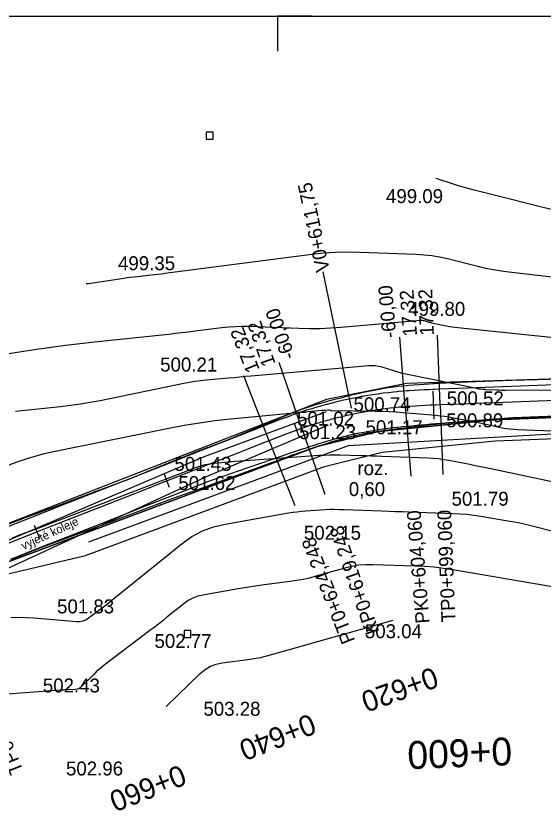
# Model space of a CAD drawing. Extents: x -636600 to -628587, y -1090963 to -1085869.
# Drawn here: x -629674.7 to -629599.1, y -1089305.8 to -1089190 of the extents above; entities that cross this region are included whole.
import ezdxf

# ---------------------------------------------------------------- set-up
doc = ezdxf.new("R2010")
doc.units = 0
for name, color, linetype in [('01_PARCELY_NÁVRH_PC', 7, 'Continuous'), ('06_ÚSES_IP_NAVRH', 7, 'Continuous'), ('08_LEGENDA_HV', 7, 'Continuous'), ('15', 7, 'Continuous'), ('40', 7, 'Continuous'), ('52', 7, 'Continuous'), ('Ex_Major Contours', 7, 'Continuous'), ('Ex_Minor Contours', 7, 'Continuous'), ('HEKTOMETRY100', 7, 'Continuous'), ('HEKTOMETRY20', 7, 'Continuous'), ('HL_BODY', 7, 'Continuous'), ('koty_vše', 7, 'Continuous'), ('POLOMERY', 7, 'Continuous'), ('popis', 7, 'Continuous'), ('situace_osa', 7, 'Continuous'), ('situace_těleso', 7, 'Continuous'), ('situace_vozovka', 7, 'Continuous'), ('VRCHOLY', 7, 'Continuous')]:
    doc.layers.add(name, color=color, linetype=linetype)

msp = doc.modelspace()

# ---------------------------------------------------------------- linework, layer by layer
at = {"layer": '01_PARCELY_NÁVRH_PC'}
for points in [[(-629219.96, -1089257.88), (-629393.2, -1089239.09), (-629404.84, -1089238.49), (-629532.17, -1089240), (-629618.76, -1089242.62), (-629630.23, -1089244.94), (-629692.43, -1089269.15), (-629702.88, -1089275.33), (-629709.57, -1089280.47), (-629719.03, -1089292.94), (-629735.64, -1089330.23), (-629741.78, -1089338.98), (-629748.13, -1089344.96), (-629754.15, -1089347.42), (-629771.79, -1089346.48), (-629796.88, -1089348.54), (-629815.64, -1089354.58), (-629845.21, -1089367.17), (-629847.27, -1089367.82)], [(-629847.27, -1089372.98), (-629830.39, -1089366.4), (-629824.12, -1089366.02), (-629805.68, -1089358.95), (-629799.19, -1089354.87), (-629780.4, -1089352.5), (-629755.55, -1089353.84), (-629747.35, -1089351.41), (-629741.75, -1089348.16), (-629736.53, -1089343.03), (-629730.9, -1089333.83), (-629715.8, -1089299.08), (-629708.65, -1089288.23), (-629702.22, -1089281.94), (-629693.51, -1089276), (-629681.41, -1089270.27), (-629631.42, -1089251.64), (-629622.77, -1089249.5), (-629606.23, -1089247.86), (-629544.07, -1089245.47), (-629416.57, -1089243.64)]]:
    msp.add_lwpolyline(points, dxfattribs=at)
msp.add_lwpolyline([(-629391.26, -1089246.28), (-629410.87, -1089245.47), (-629416.57, -1089243.64), (-629544.07, -1089245.47), (-629606.23, -1089247.86), (-629622.77, -1089249.5), (-629631.42, -1089251.64), (-629681.41, -1089270.27), (-629685.4, -1089272.16), (-629664.77, -1089267.27), (-629630.53, -1089254.51), (-629622.26, -1089252.46), (-629606.02, -1089250.85), (-629543.99, -1089248.47), (-629417.02, -1089246.65)], close=True, dxfattribs=at)
at = {"layer": '06_ÚSES_IP_NAVRH'}
msp.add_lwpolyline([(-629416.96, -1089245.08), (-629541.78, -1089246.72), (-629627.12, -1089251.56), (-629664.34, -1089265.4)], dxfattribs=at)
at = {"layer": '08_LEGENDA_HV'}
msp.add_line((-629847.27, -1089189.97), (-629007.27, -1089189.97), dxfattribs=at)
msp.add_lwpolyline([(-629632.27, -1089189.97), (-629637.27, -1089189.97), (-629637.27, -1089194.97)], dxfattribs=at)
at = {"layer": '40'}
for p, q in [((-629647.87, -1089253.16), (-629630.2, -1089246.66)), ((-629630, -1089248.61), (-629647.24, -1089255.9)), ((-629680.71, -1089267.18), (-629647.87, -1089253.16)), ((-629647.24, -1089255.9), (-629679.33, -1089270.72))]:
    msp.add_line(p, q, dxfattribs=at)
at = {"layer": '52'}
for points in [[(-629647.47, -1089207.61), (-629646.47, -1089207.61), (-629646.47, -1089206.61), (-629647.47, -1089206.61)], [(-629650.65, -1089279.05), (-629649.65, -1089279.05), (-629649.65, -1089278.05), (-629650.65, -1089278.05)]]:
    msp.add_lwpolyline(points, close=True, dxfattribs=at)
at = {"layer": 'Ex_Major Contours'}
for points in [[(-629689.6, -1089240.47), (-629671.78, -1089237.73), (-629669.71, -1089237.43), (-629667.63, -1089237.15), (-629665.55, -1089236.89), (-629663.47, -1089236.66), (-629652.86, -1089235.55), (-629651.91, -1089235.44), (-629650.95, -1089235.34), (-629650, -1089235.22), (-629649.05, -1089235.1), (-629645.24, -1089234.61), (-629644.29, -1089234.5), (-629643.34, -1089234.44), (-629642.38, -1089234.42), (-629641.42, -1089234.43), (-629634.2, -1089234.71), (-629632.68, -1089234.74), (-629631.15, -1089234.73), (-629629.63, -1089234.67), (-629628.11, -1089234.56), (-629616.75, -1089233.56), (-629616.61, -1089233.55), (-629616.48, -1089233.56), (-629616.35, -1089233.58), (-629616.21, -1089233.62), (-629615.69, -1089233.78), (-629615.56, -1089233.82), (-629615.43, -1089233.86), (-629615.29, -1089233.89), (-629615.16, -1089233.92), (-629613.01, -1089234.36), (-629612.6, -1089234.44), (-629612.19, -1089234.5), (-629611.79, -1089234.56), (-629611.38, -1089234.61), (-629598.07, -1089235.97)], [(-629588.58, -1089273.37), (-629612.11, -1089269.36), (-629613.45, -1089269.15), (-629614.8, -1089268.99), (-629616.15, -1089268.88), (-629617.5, -1089268.81), (-629623.57, -1089268.61), (-629624.59, -1089268.61), (-629625.61, -1089268.7), (-629626.62, -1089268.86), (-629627.61, -1089269.1), (-629631.74, -1089270.28), (-629632.65, -1089270.52), (-629633.57, -1089270.73), (-629634.5, -1089270.9), (-629635.43, -1089271.04), (-629639.17, -1089271.52), (-629640.1, -1089271.65), (-629641.03, -1089271.79), (-629641.96, -1089271.93), (-629642.89, -1089272.09), (-629647.93, -1089272.96), (-629648.68, -1089273.14), (-629649.38, -1089273.41), (-629650.05, -1089273.76), (-629650.67, -1089274.2), (-629653.1, -1089276.15), (-629653.7, -1089276.64), (-629654.32, -1089277.12), (-629654.93, -1089277.6), (-629655.55, -1089278.07), (-629662.09, -1089283.02), (-629662.49, -1089283.33), (-629662.87, -1089283.66), (-629663.24, -1089283.99), (-629663.6, -1089284.34), (-629665.33, -1089286.09), (-629665.53, -1089286.26), (-629665.75, -1089286.39), (-629665.99, -1089286.47), (-629666.25, -1089286.5), (-629667.34, -1089286.55), (-629667.61, -1089286.57), (-629667.89, -1089286.58), (-629668.16, -1089286.6), (-629668.43, -1089286.62), (-629687.84, -1089288.1)]]:
    msp.add_lwpolyline(points, dxfattribs=at)
at = {"layer": 'Ex_Minor Contours'}
for points in [[(-629563.97, -1089210.46), (-629567.38, -1089212.24), (-629568.28, -1089212.7), (-629569.17, -1089213.15), (-629570.08, -1089213.59), (-629570.99, -1089214.02), (-629581.36, -1089218.83), (-629582.53, -1089219.28), (-629583.73, -1089219.56), (-629584.95, -1089219.67), (-629586.21, -1089219.61), (-629591.28, -1089219.03), (-629592.55, -1089218.87), (-629593.81, -1089218.66), (-629595.06, -1089218.41), (-629596.3, -1089218.12), (-629609.03, -1089214.92), (-629609.74, -1089214.74), (-629610.45, -1089214.54), (-629611.16, -1089214.33), (-629611.87, -1089214.11), (-629614.49, -1089213.26)], [(-629664.68, -1089228.31), (-629664.35, -1089228.3), (-629659.27, -1089227.52), (-629658.78, -1089227.45), (-629658.3, -1089227.38), (-629657.81, -1089227.32), (-629657.32, -1089227.27), (-629655.37, -1089227.06), (-629654.88, -1089227.01), (-629654.39, -1089226.95), (-629653.9, -1089226.89), (-629653.42, -1089226.83), (-629632.34, -1089224.1), (-629630.63, -1089223.91), (-629628.91, -1089223.8), (-629627.18, -1089223.76), (-629625.46, -1089223.79), (-629617.35, -1089224.09), (-629616.22, -1089224.17), (-629615.1, -1089224.3), (-629614, -1089224.48), (-629612.89, -1089224.73), (-629608.51, -1089225.83), (-629607.41, -1089226.09), (-629606.3, -1089226.31), (-629605.19, -1089226.49), (-629604.07, -1089226.64), (-629586.25, -1089228.69)], [(-629674.83, -1089246.6), (-629668.37, -1089245.92), (-629666.94, -1089245.76), (-629665.51, -1089245.55), (-629664.09, -1089245.32), (-629662.68, -1089245.05), (-629650.7, -1089242.6), (-629649.9, -1089242.45), (-629649.1, -1089242.32), (-629648.29, -1089242.21), (-629647.49, -1089242.13), (-629644.25, -1089241.82), (-629643.44, -1089241.75), (-629642.63, -1089241.67), (-629641.82, -1089241.6), (-629641.01, -1089241.53), (-629624.15, -1089240.05), (-629623.68, -1089240.03), (-629623.21, -1089240.06), (-629622.75, -1089240.14), (-629622.29, -1089240.26), (-629620.47, -1089240.84), (-629620.01, -1089240.97), (-629619.55, -1089241.1), (-629619.08, -1089241.21), (-629618.62, -1089241.31), (-629608.49, -1089243.37), (-629608.41, -1089243.38), (-629608.33, -1089243.4), (-629608.25, -1089243.41), (-629608.16, -1089243.42), (-629607.83, -1089243.45), (-629607.75, -1089243.46), (-629607.66, -1089243.47), (-629607.58, -1089243.47), (-629607.5, -1089243.48), (-629605.81, -1089243.55), (-629605.5, -1089243.56), (-629605.19, -1089243.57), (-629604.88, -1089243.57), (-629604.57, -1089243.58), (-629591.68, -1089243.53)], [(-629681.35, -1089256.38), (-629674.56, -1089253.87), (-629673.28, -1089253.43), (-629671.99, -1089253.04), (-629670.68, -1089252.69), (-629669.36, -1089252.39), (-629652.81, -1089249.02), (-629650.62, -1089248.6), (-629648.42, -1089248.25), (-629646.21, -1089247.95), (-629644, -1089247.71), (-629630.86, -1089246.48), (-629630.77, -1089246.47), (-629630.67, -1089246.47), (-629630.58, -1089246.46), (-629630.49, -1089246.45), (-629630.02, -1089246.41), (-629629.97, -1089246.41), (-629629.93, -1089246.41), (-629629.88, -1089246.42), (-629629.84, -1089246.43), (-629629.66, -1089246.48), (-629629.62, -1089246.5), (-629629.58, -1089246.5), (-629629.53, -1089246.51), (-629629.49, -1089246.51), (-629623.23, -1089246.58), (-629622.23, -1089246.6), (-629621.23, -1089246.64), (-629620.23, -1089246.7), (-629619.24, -1089246.78), (-629614.54, -1089247.19), (-629613.9, -1089247.25), (-629613.26, -1089247.33), (-629612.63, -1089247.43), (-629612, -1089247.55), (-629609.3, -1089248.07), (-629608.76, -1089248.18), (-629608.22, -1089248.28), (-629607.68, -1089248.4), (-629607.15, -1089248.51), (-629605, -1089248.97), (-629604.46, -1089249.07), (-629603.92, -1089249.15), (-629603.38, -1089249.2), (-629602.83, -1089249.23), (-629586.59, -1089249.83)], [(-629675.25, -1089264.74), (-629674.33, -1089264.4), (-629673.41, -1089264.06), (-629672.49, -1089263.71), (-629671.58, -1089263.36), (-629648.97, -1089254.68), (-629648.3, -1089254.45), (-629647.61, -1089254.26), (-629646.91, -1089254.13), (-629646.21, -1089254.04), (-629643.36, -1089253.78), (-629642.64, -1089253.72), (-629641.93, -1089253.66), (-629641.22, -1089253.61), (-629640.5, -1089253.56), (-629631.28, -1089252.93), (-629630.54, -1089252.89), (-629629.79, -1089252.86), (-629629.04, -1089252.86), (-629628.29, -1089252.87), (-629625.3, -1089252.95), (-629624.55, -1089252.97), (-629623.8, -1089252.99), (-629623.06, -1089253.02), (-629622.31, -1089253.04), (-629615.71, -1089253.29), (-629614.94, -1089253.33), (-629614.18, -1089253.4), (-629613.42, -1089253.51), (-629612.67, -1089253.64), (-629609.66, -1089254.22), (-629608.9, -1089254.37), (-629608.15, -1089254.52), (-629607.4, -1089254.68), (-629606.65, -1089254.84), (-629596.54, -1089256.99)], [(-629675.47, -1089276.17), (-629674.37, -1089276.15), (-629673.27, -1089276.18), (-629672.17, -1089276.25), (-629666.07, -1089276.76), (-629665.6, -1089276.76), (-629665.15, -1089276.67), (-629664.73, -1089276.5), (-629664.33, -1089276.25), (-629662.79, -1089275.09), (-629662.4, -1089274.79), (-629662.02, -1089274.5), (-629661.64, -1089274.2), (-629661.26, -1089273.89), (-629650.92, -1089265.57), (-629649.51, -1089264.58), (-629648.02, -1089263.78), (-629646.43, -1089263.18), (-629644.75, -1089262.78), (-629635.66, -1089261.2), (-629635.04, -1089261.1), (-629634.42, -1089261.02), (-629633.79, -1089260.95), (-629633.17, -1089260.9), (-629629.76, -1089260.67), (-629629.58, -1089260.66), (-629629.41, -1089260.66), (-629629.24, -1089260.65), (-629629.06, -1089260.66), (-629628.36, -1089260.68), (-629628.19, -1089260.68), (-629628.02, -1089260.69), (-629627.84, -1089260.69), (-629627.67, -1089260.7), (-629622.27, -1089260.9), (-629621.31, -1089260.93), (-629620.35, -1089260.97), (-629619.39, -1089261), (-629618.43, -1089261.03), (-629612.05, -1089261.25), (-629611.06, -1089261.3), (-629610.08, -1089261.38), (-629609.1, -1089261.5), (-629608.12, -1089261.65), (-629604.23, -1089262.31), (-629603.26, -1089262.49), (-629602.29, -1089262.68), (-629601.33, -1089262.9), (-629600.37, -1089263.13), (-629591.39, -1089265.43)], [(-629653.23, -1089288.92), (-629648.32, -1089284.19), (-629647.63, -1089283.62), (-629646.87, -1089283.18), (-629646.05, -1089282.86), (-629645.17, -1089282.68), (-629641.51, -1089282.2), (-629640.6, -1089282.07), (-629639.69, -1089281.9), (-629638.8, -1089281.7), (-629637.91, -1089281.46), (-629620.67, -1089276.55)]]:
    msp.add_lwpolyline(points, dxfattribs=at)
at = {"layer": 'HEKTOMETRY100'}
msp.add_lwpolyline([(-629614.8, -1089247.74), (-629614.95, -1089243.75)], dxfattribs=at)
at = {"layer": 'HEKTOMETRY20'}
for points in [[(-629634.13, -1089250.26), (-629634.8, -1089248.38)], [(-629652.72, -1089257.53), (-629653.46, -1089255.67)], [(-629671.34, -1089264.85), (-629672.07, -1089262.99)]]:
    msp.add_lwpolyline(points, dxfattribs=at)
at = {"layer": 'HL_BODY'}
for points in [[(-629613.94, -1089245.71), (-629613.55, -1089255.7)], [(-629618.93, -1089245.97), (-629618.13, -1089255.94)], [(-629633.75, -1089249.07), (-629630.48, -1089258.52)], [(-629638.43, -1089250.84), (-629634.77, -1089260.14)]]:
    msp.add_lwpolyline(points, dxfattribs=at)
at = {"layer": 'POLOMERY'}
for points in [[(-629618.93, -1089245.97), (-629619.73, -1089236)], [(-629613.94, -1089245.71), (-629614.32, -1089235.72)], [(-629633.75, -1089249.07), (-629637.02, -1089239.62)], [(-629638.43, -1089250.84), (-629642.09, -1089241.53)]]:
    msp.add_lwpolyline(points, dxfattribs=at)
at = {"layer": 'situace_osa'}
msp.add_lwpolyline([(-629594.89, -1089244.98), (-629599.89, -1089245.17), (-629603.54, -1089245.31), (-629604.88, -1089245.36), (-629609.88, -1089245.55), (-629613.94, -1089245.71), (-629614.65, -1089245.74), (-629614.87, -1089245.74), (-629615.36, -1089245.76), (-629616.08, -1089245.8), (-629616.79, -1089245.83), (-629617.5, -1089245.87), (-629618.22, -1089245.92), (-629618.53, -1089245.94), (-629618.93, -1089245.97), (-629619.65, -1089246.03), (-629619.86, -1089246.05), (-629620.37, -1089246.1), (-629621.09, -1089246.18), (-629621.81, -1089246.27), (-629622.52, -1089246.37), (-629623.24, -1089246.47), (-629623.95, -1089246.58), (-629624.66, -1089246.71), (-629624.82, -1089246.73), (-629625.38, -1089246.84), (-629626.09, -1089246.98), (-629626.79, -1089247.13), (-629627.5, -1089247.28), (-629628.2, -1089247.45), (-629628.91, -1089247.62), (-629629.61, -1089247.8), (-629629.69, -1089247.83), (-629630.3, -1089248), (-629631, -1089248.19), (-629631.69, -1089248.4), (-629632.38, -1089248.62), (-629633.07, -1089248.84), (-629633.75, -1089249.07), (-629634.11, -1089249.2), (-629634.43, -1089249.31), (-629634.46, -1089249.32), (-629635.1, -1089249.56), (-629635.77, -1089249.81), (-629636.44, -1089250.06), (-629637.1, -1089250.32), (-629637.77, -1089250.58), (-629638.43, -1089250.84), (-629639.13, -1089251.11), (-629643.78, -1089252.94), (-629648.09, -1089254.64), (-629648.44, -1089254.77), (-629653.09, -1089256.6), (-629657.74, -1089258.43), (-629662.4, -1089260.26), (-629667.05, -1089262.09), (-629671.7, -1089263.92), (-629676.36, -1089265.75)], dxfattribs=at)
at = {"layer": 'situace_těleso'}
for points in [[(-629677.32, -1089263.31), (-629672.63, -1089261.57), (-629667.94, -1089259.83), (-629663.25, -1089258.09), (-629658.57, -1089256.33), (-629653.94, -1089254.43), (-629649.31, -1089252.57), (-629648.96, -1089252.43), (-629644.62, -1089250.83), (-629640, -1089248.89), (-629639.31, -1089248.6), (-629638.66, -1089248.31), (-629637.99, -1089248.03), (-629637.33, -1089247.74), (-629636.65, -1089247.46), (-629635.97, -1089247.18), (-629635.32, -1089246.93), (-629635.29, -1089246.91), (-629634.96, -1089246.79), (-629634.59, -1089246.65), (-629633.89, -1089246.38), (-629633.17, -1089246.13), (-629632.46, -1089245.9), (-629631.74, -1089245.66), (-629631.02, -1089245.44), (-629630.38, -1089245.26), (-629630.29, -1089245.23), (-629629.56, -1089245.04), (-629628.83, -1089244.85), (-629628.1, -1089244.67), (-629627.37, -1089244.47), (-629626.63, -1089244.28), (-629625.9, -1089244.1), (-629625.32, -1089243.96), (-629625.16, -1089243.93), (-629624.42, -1089243.77), (-629623.68, -1089243.62), (-629622.93, -1089243.48), (-629622.18, -1089243.35), (-629621.43, -1089243.23), (-629620.68, -1089243.12), (-629620.15, -1089243.05), (-629619.93, -1089243.03), (-629619.17, -1089242.95), (-629618.75, -1089242.91), (-629618.43, -1089242.88), (-629617.68, -1089242.82), (-629616.95, -1089242.77), (-629616.22, -1089242.72), (-629615.49, -1089242.68), (-629615, -1089242.65), (-629614.77, -1089242.64), (-629614.05, -1089242.6), (-629610, -1089242.4), (-629605, -1089242.21), (-629603.66, -1089242.17), (-629600, -1089242.07), (-629595.01, -1089241.92)], [(-629594.8, -1089247.23), (-629599.8, -1089247.47), (-629603.45, -1089247.65), (-629604.79, -1089247.76), (-629609.78, -1089248.1), (-629613.83, -1089248.42), (-629614.54, -1089248.5), (-629614.76, -1089248.52), (-629615.25, -1089248.57), (-629615.95, -1089248.65), (-629616.64, -1089248.74), (-629617.33, -1089248.82), (-629618.01, -1089248.92), (-629618.3, -1089248.96), (-629618.69, -1089249), (-629619.37, -1089249.08), (-629619.57, -1089249.1), (-629620.05, -1089249.15), (-629620.73, -1089249.22), (-629621.41, -1089249.31), (-629622.09, -1089249.4), (-629622.77, -1089249.5), (-629623.45, -1089249.61), (-629624.13, -1089249.73), (-629624.27, -1089249.76), (-629624.8, -1089249.86), (-629625.47, -1089250), (-629626.14, -1089250.15), (-629626.81, -1089250.3), (-629627.47, -1089250.47), (-629628.14, -1089250.64), (-629628.8, -1089250.83), (-629628.88, -1089250.85), (-629629.46, -1089251.02), (-629630.11, -1089251.22), (-629630.77, -1089251.42), (-629631.42, -1089251.64), (-629632.07, -1089251.86), (-629632.71, -1089252.09), (-629633.05, -1089252.21), (-629633.35, -1089252.31), (-629633.39, -1089252.32), (-629634, -1089252.52), (-629634.66, -1089252.75), (-629635.31, -1089252.98), (-629635.97, -1089253.22), (-629636.64, -1089253.46), (-629637.3, -1089253.71), (-629638.01, -1089253.97), (-629642.7, -1089255.7), (-629647.06, -1089257.27), (-629647.4, -1089257.41), (-629652.12, -1089259.06), (-629656.8, -1089260.83), (-629661.48, -1089262.59), (-629666.17, -1089264.33), (-629670.86, -1089266.06), (-629675.51, -1089267.9)]]:
    msp.add_lwpolyline(points, dxfattribs=at)
at = {"layer": 'situace_vozovka'}
for points in [[(-629594.98, -1089242.73), (-629599.97, -1089242.92), (-629603.63, -1089243.06), (-629604.97, -1089243.11), (-629609.96, -1089243.3), (-629614.02, -1089243.46), (-629614.74, -1089243.49), (-629614.96, -1089243.5), (-629615.46, -1089243.52), (-629616.18, -1089243.55), (-629616.91, -1089243.58), (-629617.64, -1089243.62), (-629618.37, -1089243.67), (-629618.69, -1089243.69), (-629619.11, -1089243.73), (-629619.86, -1089243.79), (-629620.08, -1089243.81), (-629620.6, -1089243.86), (-629621.35, -1089243.95), (-629622.09, -1089244.04), (-629622.84, -1089244.14), (-629623.58, -1089244.25), (-629624.32, -1089244.36), (-629625.06, -1089244.49), (-629625.22, -1089244.52), (-629625.8, -1089244.63), (-629626.53, -1089244.77), (-629627.27, -1089244.93), (-629628, -1089245.09), (-629628.73, -1089245.26), (-629629.46, -1089245.44), (-629630.19, -1089245.63), (-629630.28, -1089245.65), (-629630.91, -1089245.83), (-629631.63, -1089246.03), (-629632.35, -1089246.25), (-629633.07, -1089246.47), (-629633.78, -1089246.71), (-629634.49, -1089246.95), (-629634.86, -1089247.08), (-629635.19, -1089247.19), (-629635.22, -1089247.21), (-629635.88, -1089247.44), (-629636.56, -1089247.7), (-629637.24, -1089247.96), (-629637.92, -1089248.22), (-629638.59, -1089248.48), (-629639.26, -1089248.74), (-629639.96, -1089249.02), (-629644.61, -1089250.85), (-629648.91, -1089252.54), (-629649.26, -1089252.68), (-629653.91, -1089254.51), (-629658.57, -1089256.34), (-629663.22, -1089258.17), (-629667.87, -1089260), (-629672.53, -1089261.83), (-629677.18, -1089263.66)], [(-629594.8, -1089247.23), (-629599.8, -1089247.42), (-629603.45, -1089247.56), (-629604.79, -1089247.66), (-629609.78, -1089248.05), (-629613.83, -1089248.37), (-629614.54, -1089248.43), (-629614.77, -1089248.45), (-629615.25, -1089248.48), (-629615.95, -1089248.54), (-629616.65, -1089248.61), (-629617.34, -1089248.67), (-629618.02, -1089248.75), (-629618.32, -1089248.78), (-629618.7, -1089248.81), (-629619.39, -1089248.87), (-629619.59, -1089248.89), (-629620.07, -1089248.94), (-629620.76, -1089249.01), (-629621.44, -1089249.1), (-629622.12, -1089249.19), (-629622.81, -1089249.29), (-629623.49, -1089249.4), (-629624.16, -1089249.51), (-629624.31, -1089249.54), (-629624.84, -1089249.64), (-629625.52, -1089249.77), (-629626.19, -1089249.91), (-629626.86, -1089250.06), (-629627.54, -1089250.22), (-629628.2, -1089250.38), (-629628.87, -1089250.56), (-629628.95, -1089250.58), (-629629.54, -1089250.74), (-629630.2, -1089250.93), (-629630.86, -1089251.13), (-629631.52, -1089251.33), (-629632.17, -1089251.55), (-629632.82, -1089251.77), (-629633.16, -1089251.89), (-629633.47, -1089251.98), (-629633.51, -1089251.99), (-629634.13, -1089252.19), (-629634.79, -1089252.41), (-629635.45, -1089252.63), (-629636.11, -1089252.85), (-629636.78, -1089253.09), (-629637.46, -1089253.32), (-629638.17, -1089253.57), (-629642.89, -1089255.21), (-629647.27, -1089256.73), (-629647.61, -1089256.87), (-629652.27, -1089258.7), (-629656.92, -1089260.53), (-629661.57, -1089262.36), (-629666.23, -1089264.19), (-629670.88, -1089266.02), (-629675.53, -1089267.85)]]:
    msp.add_lwpolyline(points, dxfattribs=at)
at = {"layer": 'VRCHOLY'}
msp.add_lwpolyline([(-629626.62, -1089246.19), (-629630.72, -1089226.62)], dxfattribs=at)

# ---------------------------------------------------------------- texts
at = {"layer": '15'}
msp.add_text('vyjeté koleje', height=1.2, rotation=24.7887, dxfattribs=at).set_placement((-629673.66, -1089266.52))
at = {"layer": 'HEKTOMETRY100'}
msp.add_text('0+600', height=4, rotation=182.275, dxfattribs=at).set_placement((-629603.7, -1089293.34))
at = {"layer": 'HEKTOMETRY20'}
for s, rotation, p in [('0+620', 199.7458, (-629614.91, -1089283.21)), ('0+640', 201.469, (-629632.53, -1089289.89)), ('0+660', 201.469, (-629651.14, -1089297.21))]:
    msp.add_text(s, height=3, rotation=rotation, dxfattribs=at).set_placement(p)
at = {"layer": 'HL_BODY'}
for s, rotation, p in [('PK0+604,060', 94.5779, (-629615.44, -1089276.97)), ('TP0+599,060', 92.1906, (-629611.74, -1089276.83)), ('KP0+619,248', 109.0817, (-629622.62, -1089278.21)), ('PT0+624,248', 111.469, (-629626.09, -1089279.49)), ('TP0+675,357', 111.469, (-629673.65, -1089298.2))]:
    msp.add_text(s, height=2, rotation=rotation, dxfattribs=at).set_placement(p)
at = {"layer": 'koty_vše'}
for s, p in [('499.09', (-629621.69, -1089216.77)), ('499.35', (-629660.11, -1089226.39)), ('499.80', (-629618.51, -1089232.94)), ('500.21', (-629654.07, -1089240.92)), ('500.74', (-629626.35, -1089246.61)), ('500.52', (-629612.99, -1089245.76)), ('501.02', (-629634.45, -1089248.66)), ('500.89', (-629613.06, -1089248.91)), ('501.17', (-629624.62, -1089249.91)), ('501.23', (-629634.16, -1089250.61)), ('501.43', (-629652.03, -1089255.16)), ('501.62', (-629651.46, -1089257.9)), ('501.79', (-629612.29, -1089260.16)), ('502.15', (-629633.46, -1089265.03)), ('501.83', (-629668.85, -1089275.59)), ('503.04', (-629624.72, -1089279.15)), ('502.77', (-629654.88, -1089280.55)), ('502.43', (-629670.89, -1089286.93)), ('503.28', (-629647.87, -1089290.27)), ('502.96', (-629667.57, -1089298.83))]:
    msp.add_text(s, height=2, dxfattribs=at).set_placement(p)
at = {"layer": 'POLOMERY'}
for s, rotation, p in [('-60,00', 94.5779, (-629620.22, -1089236.04)), ('17,32', 94.5779, (-629617.23, -1089235.8)), ('17,32', 92.1906, (-629614.82, -1089235.73)), ('-60,00', 109.0817, (-629634.66, -1089238.81)), ('17,32', 109.0817, (-629637.5, -1089239.79)), ('17,32', 111.469, (-629639.77, -1089240.62))]:
    msp.add_text(s, height=2, rotation=rotation, dxfattribs=at).set_placement(p)
at = {"layer": 'popis'}
for s, p in [('roz.', (-629625.79, -1089255.77)), ('0,60', (-629627.03, -1089258.77))]:
    msp.add_text(s, height=2, dxfattribs=at).set_placement(p)
at = {"layer": 'VRCHOLY'}
msp.add_text('V0+611,75', height=2, rotation=101.8298, dxfattribs=at).set_placement((-629629.74, -1089226.41))

doc.saveas('drawing.dxf')
